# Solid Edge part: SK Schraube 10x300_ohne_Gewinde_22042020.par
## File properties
Author: fknapp
Template: Normal.par
Last saved by: fknapp
Revision: 14
Application: Solid Edge
Genauigkeit: 0,99
Username: fknapp
Material: Aluminium
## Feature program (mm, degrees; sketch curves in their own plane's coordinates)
sketch for "unnamed RevolvedProtrusion 1" plane through (0, 0, 0) normal (0, 0, 1) x-axis (1, 0, 0)
  line (0, 54) -> (9, 54)
  line (9, 54) -> (9, 53)
  line (9, 53) -> (5, 49)
  line (5, -240) -> (5, 49)
  line (1, -246) -> (5, -240)
  line (0, -246) -> (1, -246)
revolve "unnamed RevolvedProtrusion 1" add finite 360 deg about sketch line (0, 54) -> (0, -246)
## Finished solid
Body 1: solid body, 6 faces, 5 edges, 0 vertices.
  Faces by surface: cone 2, cylinder 2, plane 2
  Edges by curve: circle 5
Bounding box of the edges (mm): 18.000 x 300.000 x 18.000, from (-9, -246, -9) to (9, 54, 9).
Cylindrical faces by radius (mm): R5 x1, R9 x1
Conical faces (half-angle, radius in mm at the cone's reference point): 33.6901 deg R5 x1, 45 deg R9 x1
Planar faces by outward normal: +y 1, -y 1
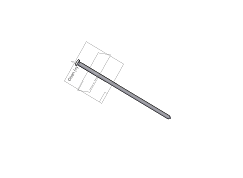
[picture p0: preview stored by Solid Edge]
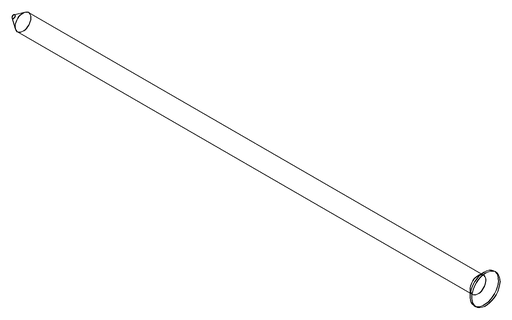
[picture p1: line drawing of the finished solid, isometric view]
